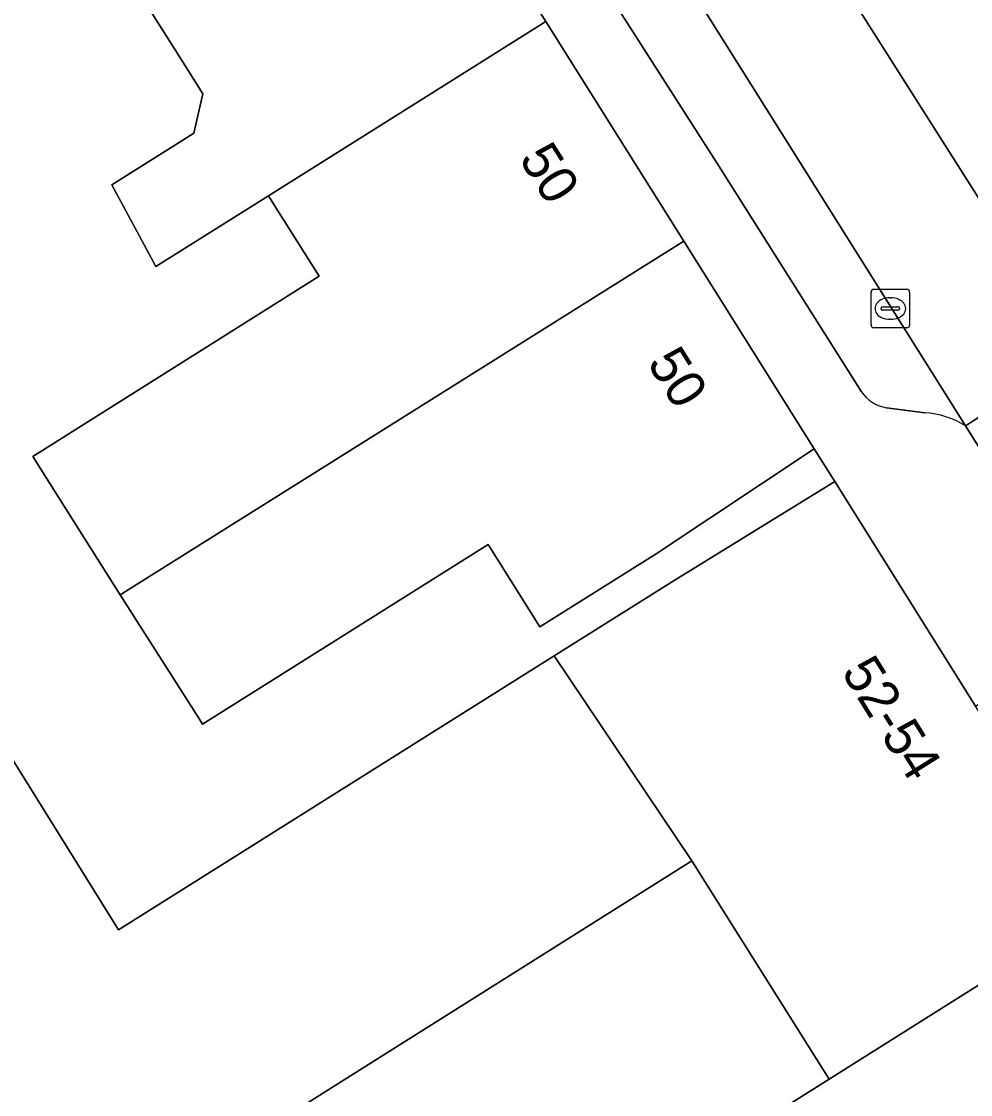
# Model space of a CAD drawing. Extents: x 161798 to 162385, y 382315 to 382833.
# Drawn here: x 162052.11 to 162076.75, y 382509.43 to 382537.31 of the extents above; entities that cross this region are included whole.
import ezdxf

# ---------------------------------------------------------------- set-up
doc = ezdxf.new("R2010")
doc.units = 0
for name, color, linetype in [('IMGEO_Erf', 7, 'Continuous'), ('IMGEO_Kolk', 7, 'Continuous'), ('IMGEO_Pand', 7, 'Continuous'), ('IMGEO_Pand_nummerreeks', 7, 'Continuous'), ('IMGEO_Parkeervlak_open', 7, 'Continuous'), ('IMGEO_Rijbaan_lokaal_open', 7, 'Continuous'), ('IMGEO_Voetpad_open', 7, 'Continuous')]:
    doc.layers.add(name, color=color, linetype=linetype)

msp = doc.modelspace()

# ---------------------------------------------------------------- linework, layer by layer
at = {"layer": 'IMGEO_Erf'}
msp.add_lwpolyline([(162046.977, 382526.001), (162054.63, 382513.705), (162065.94, 382520.822), (162069.058, 382522.785), (162073.232, 382525.358), (162072.69, 382526.201), (162068.589, 382523.477), (162065.573, 382521.582), (162064.227, 382523.721), (162056.811, 382519.053), (162056.716, 382519.203), (162054.668, 382522.408), (162054.505, 382522.667), (162053.882, 382523.657), (162052.403, 382526.006), (162059.841, 382530.688), (162058.681, 382532.53), (162058.524, 382532.779), (162055.598, 382530.942), (162054.452, 382533.065), (162055.693, 382533.844), (162056.201, 382534.163), (162056.581, 382534.402), (162056.815, 382535.43), (162056.097, 382536.574), (162055.064, 382538.219)], dxfattribs=at)
msp.add_lwpolyline([(162073.086, 382509.829), (162069.515, 382515.498), (162057.823, 382508.133), (162057.663, 382508.386), (162052.472, 382505.116), (162047.706, 382502.114), (162051.506, 382496.234), (162056.204, 382499.194), (162061.395, 382502.464)], close=True, dxfattribs=at)
at = {"layer": 'IMGEO_Kolk'}
for p, q in [((162074.245, 382530.349), (162075.097, 382530.349)), ((162074.17, 382529.423), (162074.17, 382530.275)), ((162074.658, 382530.129), (162074.683, 382530.129)), ((162075.171, 382530.275), (162075.171, 382529.423)), ((162074.429, 382529.843), (162074.429, 382529.855)), ((162074.867, 382529.806), (162074.469, 382529.806)), ((162074.472, 382529.892), (162074.87, 382529.892)), ((162074.913, 382529.855), (162074.913, 382529.843)), ((162074.681, 382529.569), (162074.656, 382529.569)), ((162075.097, 382529.349), (162074.245, 382529.349))]:
    msp.add_line(p, q, dxfattribs=at)
for points in [[(162074.245, 382530.349), (162075.097, 382530.349)], [(162074.17, 382529.423), (162074.17, 382530.275)], [(162075.171, 382530.275), (162075.171, 382529.423)], [(162075.097, 382529.349), (162074.245, 382529.349)]]:
    msp.add_lwpolyline(points, dxfattribs=at)
for centre, radius, start, end in [((162074.247, 382530.273), 0.0765, 91.552, 178.448), ((162074.247, 382530.273), 0.0765, 91.552, 178.448), ((162075.095, 382530.273), 0.0765, 1.552, 88.448), ((162075.095, 382530.273), 0.0765, 1.552, 88.448), ((162074.469, 382529.852), 0.0403, 85.8775, 175.7526), ((162074.466, 382529.842), 0.0366, 178.938, 274.7102), ((162074.87, 382529.849), 0.043, 264.8664, 352.4533), ((162074.874, 382529.854), 0.0386, 1.7309, 96.639), ((162074.247, 382529.425), 0.0765, 181.552, 268.448), ((162074.247, 382529.425), 0.0765, 181.552, 268.448), ((162075.095, 382529.425), 0.0765, 271.552, 358.448), ((162075.095, 382529.425), 0.0765, 271.552, 358.448)]:
    msp.add_arc(centre, radius, start, end, dxfattribs=at)
for centre, major_axis, ratio, start_param, end_param in [((162074.657, 382529.849), (-0.387, 0.002), 0.722429, 4.712389, 7.853982), ((162074.682, 382529.849), (-0.39, 0.002), 0.717154, 1.570796, 4.712389)]:
    msp.add_ellipse(centre, major_axis=major_axis, ratio=ratio, start_param=start_param, end_param=end_param, dxfattribs=at)
at = {"layer": 'IMGEO_Pand'}
for points in [[(162065.729, 382537.304), (162062.305, 382542.767), (162055.064, 382538.219), (162056.097, 382536.574), (162056.815, 382535.43), (162056.581, 382534.402), (162056.201, 382534.163), (162055.693, 382533.844), (162054.452, 382533.065), (162055.598, 382530.942), (162058.524, 382532.779)], [(162069.305, 382531.6), (162065.729, 382537.304), (162058.524, 382532.779), (162058.681, 382532.53), (162059.841, 382530.688), (162052.403, 382526.006), (162053.882, 382523.657), (162054.505, 382522.667), (162054.668, 382522.408)], [(162064.227, 382523.721), (162065.573, 382521.582), (162068.589, 382523.477), (162072.69, 382526.201), (162069.305, 382531.6), (162054.668, 382522.408), (162056.716, 382519.203), (162056.811, 382519.053)], [(162046.977, 382526.001), (162046.923, 382526.087), (162043.605, 382524.213), (162035.998, 382519.906), (162045.105, 382506.067), (162045.963, 382504.763), (162047.706, 382502.114), (162052.472, 382505.116), (162057.663, 382508.386), (162057.823, 382508.133), (162069.515, 382515.498), (162065.94, 382520.822), (162054.63, 382513.705)], [(162076.885, 382519.522), (162073.232, 382525.358), (162069.058, 382522.785), (162065.94, 382520.822), (162069.515, 382515.498), (162073.086, 382509.829), (162080.162, 382514.287), (162078.879, 382516.336)], [(162076.158, 382504.617), (162079.27, 382506.576), (162083.329, 382509.229), (162083.059, 382509.66), (162080.162, 382514.287), (162073.086, 382509.829), (162061.395, 382502.464), (162065.677, 382495.668), (162069.012, 382497.701), (162070.016, 382498.362), (162068.91, 382500), (162067.387, 382502.256), (162071.118, 382504.604), (162072.492, 382502.422), (162075.587, 382504.275)]]:
    msp.add_lwpolyline(points, close=True, dxfattribs=at)
at = {"layer": 'IMGEO_Parkeervlak_open'}
for points in [[(162076.622, 382526.804), (162062.739, 382548.921)], [(162062.767, 382545.209), (162070.163, 382533.636), (162073.919, 382527.687)], [(162070.806, 382542.435), (162079.529, 382528.674), (162080.1, 382527.774)], [(162074.571, 382527.272), (162075.563, 382527.143)]]:
    msp.add_lwpolyline(points, dxfattribs=at)
for centre, radius, start, end in [((162074.739, 382528.256), 0.999, 214.7546, 260.2917), ((162075.416, 382524.862), 2.286, 58.1748, 86.324)]:
    msp.add_arc(centre, radius, start, end, dxfattribs=at)
at = {"layer": 'IMGEO_Rijbaan_lokaal_open'}
msp.add_lwpolyline([(162055.907, 382559.825), (162061.253, 382551.291), (162061.473, 382550.939), (162062.044, 382550.029), (162062.739, 382548.921), (162076.622, 382526.804), (162079.529, 382528.674), (162070.806, 382542.435), (162069.1, 382545.165), (162066.2, 382549.805)], dxfattribs=at)
msp.add_lwpolyline([(162079.529, 382528.674), (162076.622, 382526.804), (162078.203, 382524.285), (162081.138, 382526.129), (162080.1, 382527.774)], close=True, dxfattribs=at)
at = {"layer": 'IMGEO_Voetpad_open'}
for points in [[(162054.599, 382561.171), (162051.863, 382559.469), (162058.602, 382548.668), (162058.995, 382548.046), (162062.305, 382542.767), (162065.729, 382537.304), (162069.305, 382531.6), (162072.69, 382526.201), (162073.232, 382525.358), (162076.885, 382519.522), (162079.956, 382521.492), (162078.203, 382524.285), (162076.622, 382526.804)], [(162073.919, 382527.687), (162070.163, 382533.636), (162062.767, 382545.209)], [(162075.563, 382527.143), (162074.571, 382527.272)]]:
    msp.add_lwpolyline(points, dxfattribs=at)
for centre, radius, start, end in [((162074.739, 382528.256), 0.999, 214.7546, 260.2917), ((162075.416, 382524.862), 2.286, 58.1748, 86.324)]:
    msp.add_arc(centre, radius, start, end, dxfattribs=at)

# ---------------------------------------------------------------- texts
at = {"layer": 'IMGEO_Pand_nummerreeks'}
for s, rotation, p in [('50', 302.0854, (162065.012, 382533.741)), ('50', 302.0854, (162068.339, 382528.434)), ('52-54', 302.0453, (162073.383, 382520.405))]:
    msp.add_text(s, height=1, rotation=rotation, dxfattribs=at).set_placement(p)

doc.saveas('drawing.dxf')
